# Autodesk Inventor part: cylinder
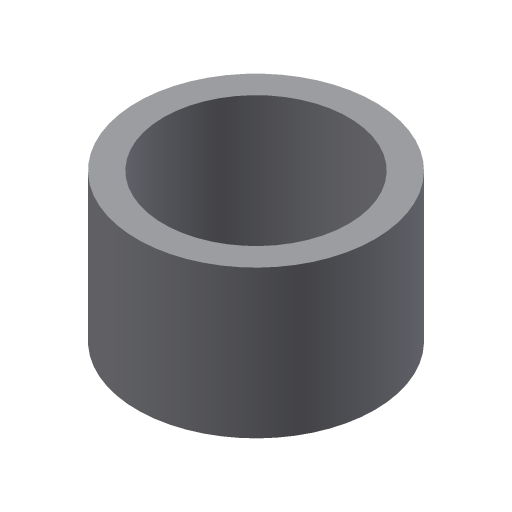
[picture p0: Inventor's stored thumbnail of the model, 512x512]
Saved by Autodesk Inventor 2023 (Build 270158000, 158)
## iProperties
Part Number: cylinder
Document SubType Name: Modeling
Created: 2003-01
Designer: Owner
Density: 1 g/cm^3
Material: Generic
Appearance: Default
Control State: 0
Master: False
Checked Out: False
Shininess: 64.0
Length Units: 11269
Angle Units: 11279
Time Units: 11290
Mass Units: 11283
Length Display Precision: 3
Angle Display Precision: 2
Compacted: True
Density: 0.0
Volumn: 0.0
Area: 0.0
PropertySet Name: Model Information
Author: Owner
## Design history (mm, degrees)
sketch "Sketch1"
  geometry: C1 r 112.5 at (0, 0); C2 r 87.5 at (0, 0)
  constraints: 2 centre point, 1 coincident, 1 concentric
  dimensions: "d0" = 225 diameter of C1; "d1" = 175 diameter of C2
extrude "Extrusion1" new body sketch "Sketch1" stored distance "d2" = 140; taper "d3" = 0 deg
body "Solid1"
